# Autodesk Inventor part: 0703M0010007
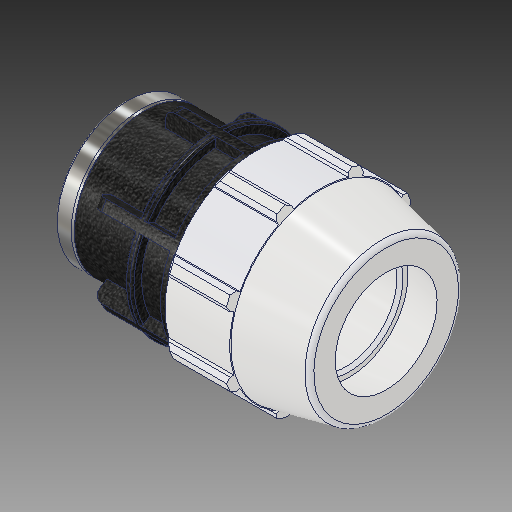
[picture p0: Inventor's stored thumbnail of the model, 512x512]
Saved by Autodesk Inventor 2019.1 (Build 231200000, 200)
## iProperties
Created: 2017-02
Part Number: 0703M0010007
Material: PVC-Piping
Description: PLASSON FEMALE ADAPTOR 1'' - 3/4''F
Document SubType Name: Modeling
Designer: KIM
Mass: 92.6774 g
Surface Area: 199.44 cm^2
Volume: 66.1981 cm^3
Density: 1.4 g/cm^3
Appearance: PTFE
Author: KIM
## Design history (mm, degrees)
derived "0703M0.ipt"
feature "Solid1::0703M0.ipt"
tag "TaggingFeature1"
body "Solid1"
other parameters: "d2" = 33.3, "d4" = 12.15571, "d5" = 21.2725, "d7" = 64.008, "d9" = 12.15571, "d11" = 2.43114, "d12" = 51.2064, "d13" = 120 deg, "d14" = 49.95, "d15" = 12 deg, "d16" = 57.6072, "d18" = 1.665, "d19" = 35 deg, "d20" = 17.5 deg, "d21" = 59.52744, "d23" = 0, "d25" = 360 deg, "d27" = 1.28016, "d34" = 3.2004, "d35" = 25.527, "d36" = 0, "d42" = 21.2725, "d43" = 1.92024, "d46" = 0.999, "d49" = 62.992, "d51" = 85.09, "d53" = 0.666, "d55" = 360 deg, "d61" = 19.05, "d62" = 26.64, "d63" = 24.117, "d64" = 28.36333, "d65" = 3.2004, "d66" = 0.5, "d67" = 1, "d68" = 5.715, "d69" = 46.08576, "d70" = 1.6002, "d_" = 33.3, "E_" = 64.008, "H_" = 85.09, "l_" = 62.992, "l_2" = 19.05, "Rp_" = 24.117
